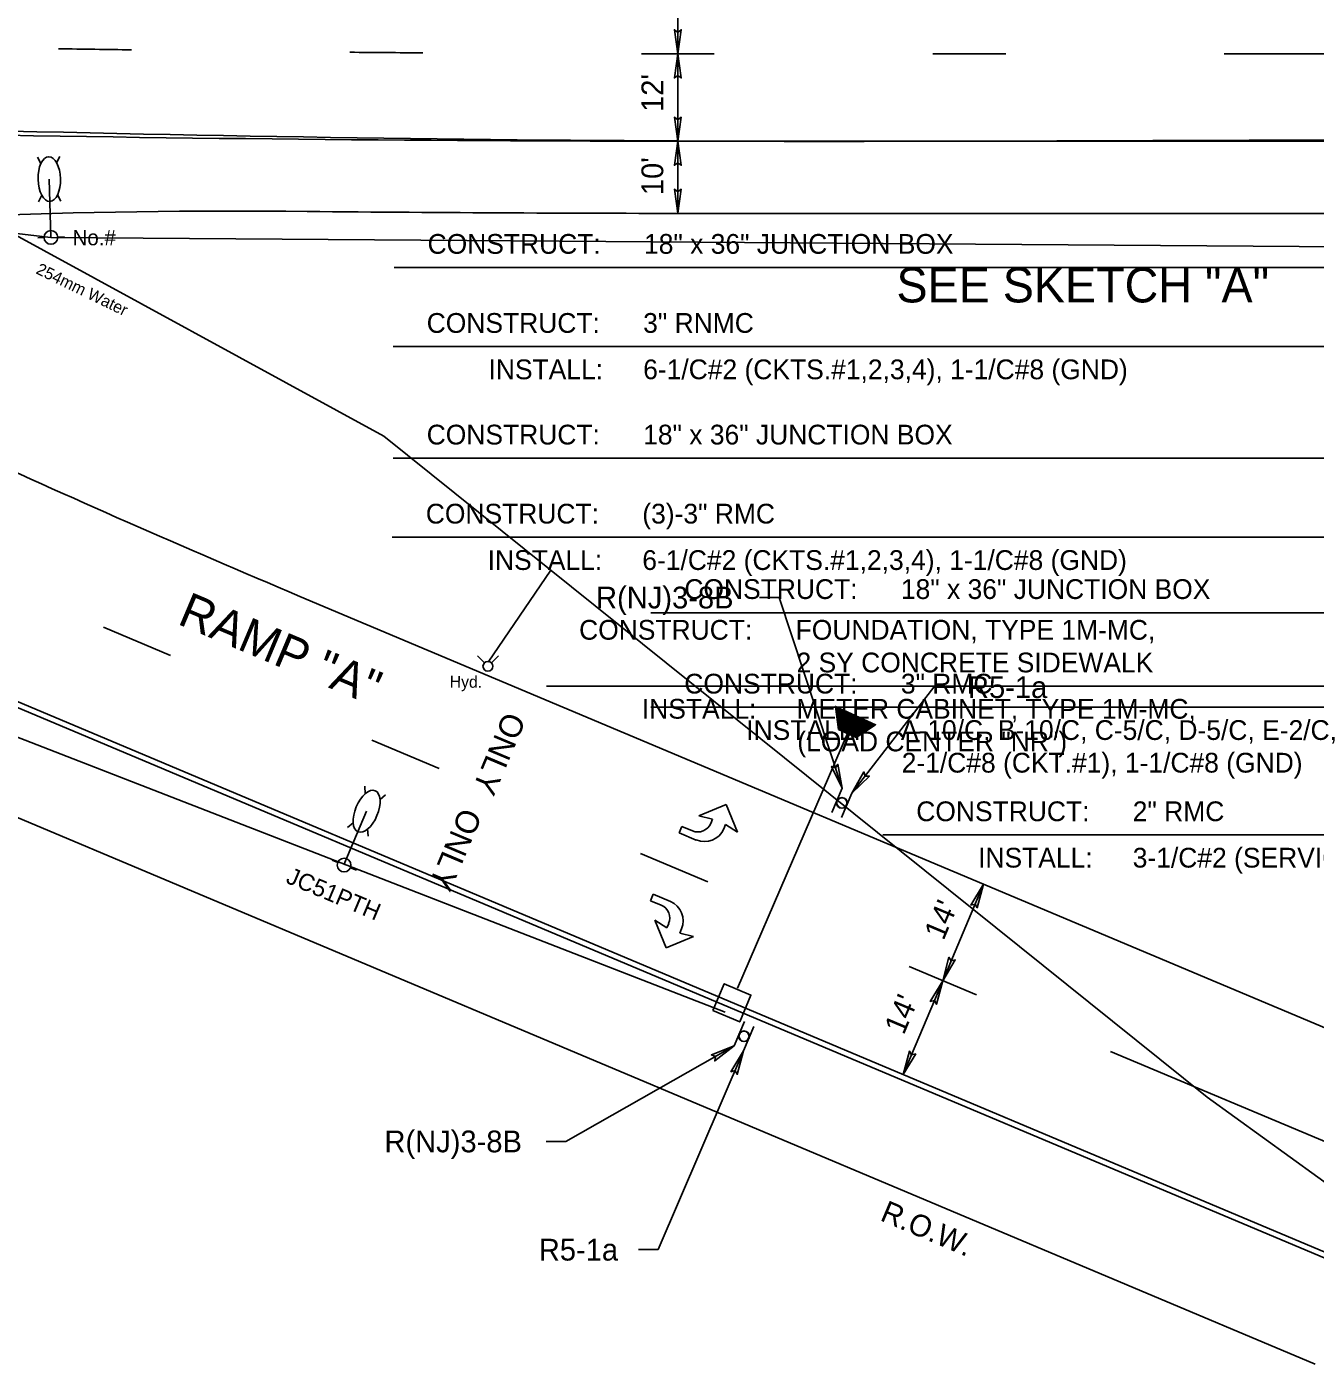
# Model space of a CAD drawing. Extents: x 488740 to 507913, y 466518 to 497949.
# Drawn here: x 503231.3 to 503408.4, y 495861.2 to 496045.1 of the extents above; entities that cross this region are included whole.
import ezdxf

# ---------------------------------------------------------------- set-up
doc = ezdxf.new("R2010")
doc.units = 0
for name, color, linetype in [('1', 7, 'Continuous'), ('10', 7, 'Continuous'), ('12', 7, 'Continuous'), ('23', 7, 'Continuous'), ('36', 7, 'Continuous'), ('38', 7, 'Continuous'), ('42', 7, 'Continuous')]:
    doc.layers.add(name, color=color, linetype=linetype)

msp = doc.modelspace()

# ---------------------------------------------------------------- linework, layer by layer
at = {"layer": '1'}
for p, q in [((503233.19, 496026.3), (503232.73, 496027.21)), ((503235.38, 496026.42), (503235.8, 496027.29)), ((503234.58, 496016.17), (503234.37, 496024.18)), ((503233.34, 496021.97), (503232.89, 496021.07)), ((503235.49, 496022.02), (503235.96, 496021.15)), ((503325.93, 496019.46), (503467, 496019.46)), ((503233.67, 496016.15), (503232.81, 496016.12)), ((503235.55, 496016.2), (503236.45, 496016.22)), ((503126.85, 495994.96), (503413.81, 495874.09)), ((503127.14, 495995.66), (503414.1, 495874.78)), ((503121.44, 495982.11), (503408.4, 495861.23)), ((503268.83, 495966.81), (503425.13, 495900.97)), ((503277.8, 495939.68), (503277.75, 495940.7)), ((503279.84, 495938.89), (503280.58, 495939.5)), ((503274.88, 495929.88), (503277.99, 495937.26)), ((503276.14, 495935.67), (503275.37, 495935.04)), ((503278.13, 495934.83), (503278.19, 495933.85)), ((503274.05, 495930.23), (503273.26, 495930.56)), ((503275.78, 495929.5), (503276.61, 495929.15))]:
    msp.add_line(p, q, dxfattribs=at)
msp.add_lwpolyline([(503325.59, 495909.86), (503327.15, 495913.55), (503330.83, 495912), (503329.28, 495908.31)], close=True, dxfattribs=at)
for centre in [(503234.59, 496016.16), (503274.89, 495929.86)]:
    msp.add_circle(centre, 0.939, dxfattribs=at)
for centre, radius, start, end in [((503260.35, 495039.95), 979.83, 89.44715, 94.92028), ((503325.29, 501769.95), 5750.49, 269.44715, 270.006342), ((503902.76, 497471.78), 1633.04, 243.53359, 247.15789)]:
    msp.add_arc(centre, radius, start, end, dxfattribs=at)
for centre, major_axis in [((503234.37, 496024.18), (0.08, -3.07)), ((503277.99, 495937.26), (-1.19, -2.83))]:
    msp.add_ellipse(centre, major_axis=major_axis, ratio=0.504, dxfattribs=at)
at = {"layer": '10'}
for p, q in [((503445.69, 495964.56), (503317.07, 495964.56)), ((503445.69, 495951.56), (503317.07, 495951.56))]:
    msp.add_line(p, q, dxfattribs=at)
at = {"layer": '12'}
for p, q in [((503410.38, 496012.02), (503281.76, 496012.02)), ((503410.26, 496001.15), (503281.64, 496001.15)), ((503410.26, 495985.8), (503281.64, 495985.8)), ((503410.15, 495974.93), (503281.52, 495974.93)), ((503431.34, 495954.47), (503302.72, 495954.47)), ((503477.57, 495934.01), (503348.94, 495934.01))]:
    msp.add_line(p, q, dxfattribs=at)
at = {"layer": '23'}
for p, q in [((503346.41, 496029.35), (503748.62, 496030.81)), ((503128.59, 496028.45), (503234.58, 496016.17)), ((503217.5, 496023.14), (503280.37, 495988.85)), ((503234.58, 496016.17), (503469.08, 496014.43)), ((503280.37, 495988.85), (503393.56, 495897.96)), ((503133.33, 495985.05), (503327.28, 495909.62)), ((503294.68, 495957.74), (503303.32, 495970.42)), ((503294.18, 495957.68), (503293.23, 495958.64)), ((503295.14, 495957.67), (503296.1, 495958.62)), ((503342.44, 495951.59), (503347.9, 495949.11)), ((503342.45, 495951.51), (503347.83, 495949.06)), ((503342.46, 495951.43), (503347.76, 495949.02)), ((503342.47, 495951.35), (503347.7, 495948.98)), ((503342.48, 495951.27), (503347.63, 495948.93)), ((503342.49, 495951.19), (503347.56, 495948.89)), ((503342.5, 495951.11), (503347.5, 495948.84)), ((503342.51, 495951.04), (503347.43, 495948.8)), ((503342.52, 495950.96), (503347.36, 495948.76)), ((503342.53, 495950.88), (503347.3, 495948.71)), ((503342.55, 495950.8), (503347.23, 495948.67)), ((503342.56, 495950.72), (503347.17, 495948.62)), ((503342.57, 495950.64), (503347.1, 495948.58)), ((503342.58, 495950.56), (503347.03, 495948.53)), ((503342.59, 495950.48), (503346.97, 495948.49)), ((503342.6, 495950.4), (503346.9, 495948.45)), ((503342.61, 495950.33), (503346.83, 495948.4)), ((503342.62, 495950.25), (503346.77, 495948.36)), ((503342.63, 495950.17), (503346.7, 495948.32)), ((503342.64, 495950.09), (503346.63, 495948.27)), ((503342.65, 495950.01), (503346.57, 495948.23)), ((503342.66, 495949.93), (503346.5, 495948.18)), ((503342.67, 495949.85), (503346.44, 495948.14)), ((503342.68, 495949.77), (503346.37, 495948.1)), ((503342.69, 495949.69), (503346.3, 495948.05)), ((503342.7, 495949.61), (503346.24, 495948.01)), ((503342.71, 495949.54), (503346.17, 495947.96)), ((503342.72, 495949.46), (503346.1, 495947.92)), ((503342.73, 495949.38), (503346.04, 495947.88)), ((503342.74, 495949.3), (503345.97, 495947.83)), ((503342.75, 495949.22), (503345.9, 495947.79)), ((503342.77, 495949.14), (503345.84, 495947.74)), ((503342.78, 495949.06), (503345.77, 495947.7)), ((503342.79, 495948.98), (503345.71, 495947.66)), ((503342.8, 495948.9), (503345.64, 495947.61)), ((503342.81, 495948.83), (503345.57, 495947.57)), ((503342.82, 495948.75), (503345.51, 495947.52)), ((503342.83, 495948.67), (503345.44, 495947.48)), ((503328.98, 495912.96), (503344.08, 495947.95)), ((503342.84, 495948.59), (503345.37, 495947.44)), ((503344.08, 495947.95), (503344.08, 495947.95)), ((503393.56, 495897.96), (503425.43, 495874.84))]:
    msp.add_line(p, q, dxfattribs=at)
msp.add_lwpolyline([(503342.85, 495948.51), (503345.31, 495947.39), (503347.96, 495949.15), (503342.43, 495951.67)], close=True, dxfattribs=at)
msp.add_circle((503294.66, 495957.2), 0.675, dxfattribs=at)
msp.add_arc((503345.84, 500783.2), 4753.85, 267.1758, 270.00684, dxfattribs=at)
at = {"layer": '36'}
for p, q in [((503315.77, 496041.39), (503325.78, 496041.39)), ((503355.83, 496041.4), (503365.85, 496041.4)), ((503395.9, 496041.4), (503445.51, 496041.4)), ((503326.93, 496029.38), (503446.17, 496029.38)), ((503241.81, 495962.57), (503251.04, 495958.68)), ((503278.73, 495947.02), (503287.96, 495943.13)), ((503323.67, 495936.64), (503327.44, 495938.18)), ((503327.44, 495938.18), (503328.98, 495934.4)), ((503325.56, 495936.19), (503323.67, 495936.64)), ((503325.31, 495935.6), (503325.56, 495936.19)), ((503320.95, 495934.31), (503321.32, 495935.19)), ((503323.31, 495933.31), (503320.95, 495934.31)), ((503321.32, 495935.19), (503322.8, 495934.57)), ((503327.34, 495935.44), (503327.09, 495934.85)), ((503328.98, 495934.4), (503327.34, 495935.44)), ((503315.65, 495931.46), (503324.89, 495927.58)), ((503317.01, 495924.97), (503317.39, 495925.86)), ((503318.49, 495924.35), (503317.01, 495924.97)), ((503317.39, 495925.86), (503319.75, 495924.86)), ((503319.16, 495918.5), (503317.62, 495922.28)), ((503317.62, 495922.28), (503319.27, 495921.24)), ((503319.27, 495921.24), (503319.52, 495921.83)), ((503321.29, 495921.08), (503321.04, 495920.49)), ((503322.94, 495920.04), (503319.16, 495918.5)), ((503321.04, 495920.49), (503322.94, 495920.04)), ((503352.58, 495915.91), (503361.81, 495912.03)), ((503380.27, 495904.25), (503419.65, 495887.66))]:
    msp.add_line(p, q, dxfattribs=at)
for centre, radius, start, end in [((503325.29, 501769.95), 5728.55, 269.10329, 269.20347), ((503325.29, 501769.95), 5728.55, 269.50401, 269.60419), ((503325.29, 501769.95), 5740.57, 267.688922, 270.016331), ((503323.54, 495936.34), 1.92, 247.157, 337.157), ((503324.43, 495935.97), 2.88, 247.157, 337.157), ((503318.63, 495922.2), 2.88, 337.157, 67.157), ((503317.74, 495922.58), 1.92, 337.157, 67.157)]:
    msp.add_arc(centre, radius, start, end, dxfattribs=at)
at = {"layer": '38'}
for p, q in [((503320.78, 496041.39), (503320.78, 496053.41)), ((503320.78, 496029.38), (503320.78, 496041.39)), ((503320.78, 496019.47), (503320.78, 496029.38)), ((503357.19, 495913.97), (503362.78, 495927.23)), ((503351.75, 495901.05), (503357.19, 495913.97))]:
    msp.add_line(p, q, dxfattribs=at)
for points in [[(503320.78, 496041.39), (503321.25, 496044.7), (503320.78, 496044.34), (503320.3, 496044.7)], [(503320.78, 496041.39), (503320.3, 496038.08), (503320.78, 496038.44), (503321.25, 496038.08)], [(503320.78, 496029.38), (503321.25, 496032.69), (503320.78, 496032.34), (503320.3, 496032.69)], [(503320.78, 496029.38), (503320.3, 496026.08), (503320.78, 496026.43), (503321.25, 496026.08)], [(503320.78, 496019.47), (503321.25, 496022.77), (503320.78, 496022.42), (503320.3, 496022.77)], [(503362.78, 495927.23), (503361.06, 495924.37), (503361.63, 495924.51), (503361.93, 495924)], [(503357.19, 495913.97), (503358.91, 495916.83), (503358.34, 495916.69), (503358.04, 495917.2)], [(503357.19, 495913.97), (503355.47, 495911.11), (503356.05, 495911.25), (503356.35, 495910.74)], [(503351.75, 495901.05), (503353.47, 495903.91), (503352.9, 495903.77), (503352.6, 495904.28)]]:
    msp.add_lwpolyline(points, close=True, dxfattribs=at)
at = {"layer": '42'}
for p, q in [((503331.99, 495966.64), (503334.7, 495966.64)), ((503343.38, 495940.44), (503334.7, 495966.64)), ((503344.71, 495939.77), (503355.98, 495954.33)), ((503355.98, 495954.33), (503358.69, 495954.33)), ((503341.96, 495937.07), (503343.38, 495940.44)), ((503344.71, 495939.77), (503343.28, 495936.39)), ((503328.5, 495904.99), (503329.92, 495908.36)), ((503331.24, 495907.69), (503329.82, 495904.31)), ((503305.38, 495891.86), (503328.5, 495904.99)), ((503318.06, 495876.99), (503329.82, 495904.31)), ((503302.67, 495891.86), (503305.38, 495891.86)), ((503315.35, 495876.99), (503318.06, 495876.99))]:
    msp.add_line(p, q, dxfattribs=at)
for points in [[(503343.38, 495940.44), (503342.79, 495943.73), (503342.46, 495943.24), (503341.9, 495943.43)], [(503344.71, 495939.77), (503347.1, 495942.09), (503346.51, 495942.1), (503346.36, 495942.67)], [(503328.5, 495904.99), (503325.39, 495903.76), (503325.93, 495903.53), (503325.86, 495902.94)], [(503329.82, 495904.31), (503328.08, 495901.46), (503328.65, 495901.6), (503328.95, 495901.09)]]:
    msp.add_lwpolyline(points, close=True, dxfattribs=at)
for centre in [(503343.3, 495938.42), (503343.36, 495938.41), (503329.84, 495906.34), (503329.9, 495906.33)]:
    msp.add_circle(centre, 0.721, dxfattribs=at)

# ---------------------------------------------------------------- texts
at = {"layer": '1'}
msp.add_text('No.#', height=2.109, dxfattribs=at).set_placement((503237.56, 496015.08))
for s, height, p in [('RAMP "A"', 4.796, (503251.83, 495963.07)), ('JC51PTH', 2.344, (503266.76, 495927.47)), ('R.O.W.', 2.993, (503348.44, 495881.07))]:
    msp.add_text(s, height=height, rotation=337.1579, dxfattribs=at).set_placement(p)
at = {"layer": '10'}
for s, height, p in [('SEE SKETCH "A"', 4.7957, (503350.83, 496007.22)), ('CONSTRUCT:', 2.716, (503321.67, 495966.45)), ('18" x 36" JUNCTION BOX                  ', 2.7163, (503351.44, 495966.45)), ('CONSTRUCT:', 2.716, (503321.67, 495953.45)), ('3" RMC                                  ', 2.7163, (503351.44, 495953.45)), ('INSTALL:', 2.716, (503330.18, 495947.07)), ('A-10/C, B-10/C, C-5/C, D-5/C, E-2/C,    ', 2.7163, (503351.44, 495947.07)), ('2-1/C#8 (CKT.#1), 1-1/C#8 (GND)         ', 2.7163, (503351.55, 495942.58))]:
    msp.add_text(s, height=height, dxfattribs=at).set_placement(p)
at = {"layer": '12'}
for s, height, p in [('CONSTRUCT:', 2.716, (503286.37, 496013.91)), ('18" x 36" JUNCTION BOX             ', 2.7163, (503316.13, 496013.91)), ('CONSTRUCT:', 2.716, (503286.25, 496003.04)), ('3" RNMC                            ', 2.7163, (503316.01, 496003.04)), ('INSTALL:', 2.716, (503294.75, 495996.66)), ('6-1/C#2 (CKTS.#1,2,3,4), 1-1/C#8 (GND)         ', 2.7163, (503316.01, 495996.66)), ('CONSTRUCT:', 2.716, (503286.25, 495987.69)), ('18" x 36" JUNCTION BOX             ', 2.7163, (503316.01, 495987.69)), ('CONSTRUCT:', 2.716, (503286.13, 495976.82)), ('(3)-3" RMC                         ', 2.7163, (503315.89, 495976.82)), ('INSTALL:', 2.716, (503294.63, 495970.44)), ('6-1/C#2 (CKTS.#1,2,3,4), 1-1/C#8 (GND)         ', 2.7163, (503315.89, 495970.44)), ('CONSTRUCT:', 2.716, (503307.2, 495960.85)), ('FOUNDATION, TYPE 1M-MC,            ', 2.7163, (503336.97, 495960.85)), ('2 SY CONCRETE SIDEWALK             ', 2.7163, (503337.09, 495956.36)), ('INSTALL:', 2.716, (503315.83, 495949.99)), ('METER CABINET, TYPE 1M-MC,                     ', 2.7163, (503337.09, 495949.99)), ('(LOAD CENTER "NR")                             ', 2.7163, (503337.2, 495945.5)), ('CONSTRUCT:', 2.716, (503353.55, 495935.9)), ('2" RMC                             ', 2.7163, (503383.31, 495935.9)), ('INSTALL:', 2.716, (503362.05, 495929.52)), ('3-1/C#2 (SERVICE WIRE)                         ', 2.7163, (503383.31, 495929.52))]:
    msp.add_text(s, height=height, dxfattribs=at).set_placement(p)
at = {"layer": '23'}
for s, height, rotation, p in [('254mm Water', 1.6205, 334.1147, (503232.42, 496011.25)), ('Hyd.', 1.62, 359.5283, (503289.41, 495954.27))]:
    msp.add_text(s, height=height, rotation=rotation, dxfattribs=at).set_placement(p)
at = {"layer": '36'}
for p in [(503297.01, 495951.13), (503290.99, 495937.94)]:
    msp.add_text('ONLY', height=3.193, rotation=247.1557, dxfattribs=at).set_placement(p)
at = {"layer": '38'}
for s, rotation, p in [("12'", 90, (503318.77, 496033.41)), ("10'", 90, (503318.77, 496021.97)), ("14'", 67.1563, (503357.3, 495919.39)), ("14'", 67.1561, (503351.83, 495906.4))]:
    msp.add_text(s, height=2.993, rotation=rotation, dxfattribs=at).set_placement(p)
at = {"layer": '42'}
for s, p in [('R(NJ)3-8B', (503309.53, 495965.15)), ('R5-1a', (503360.66, 495952.83)), ('R(NJ)3-8B', (503280.44, 495890.37)), ('R5-1a', (503301.66, 495875.49))]:
    msp.add_text(s, height=2.993, dxfattribs=at).set_placement(p)

doc.saveas('drawing.dxf')
